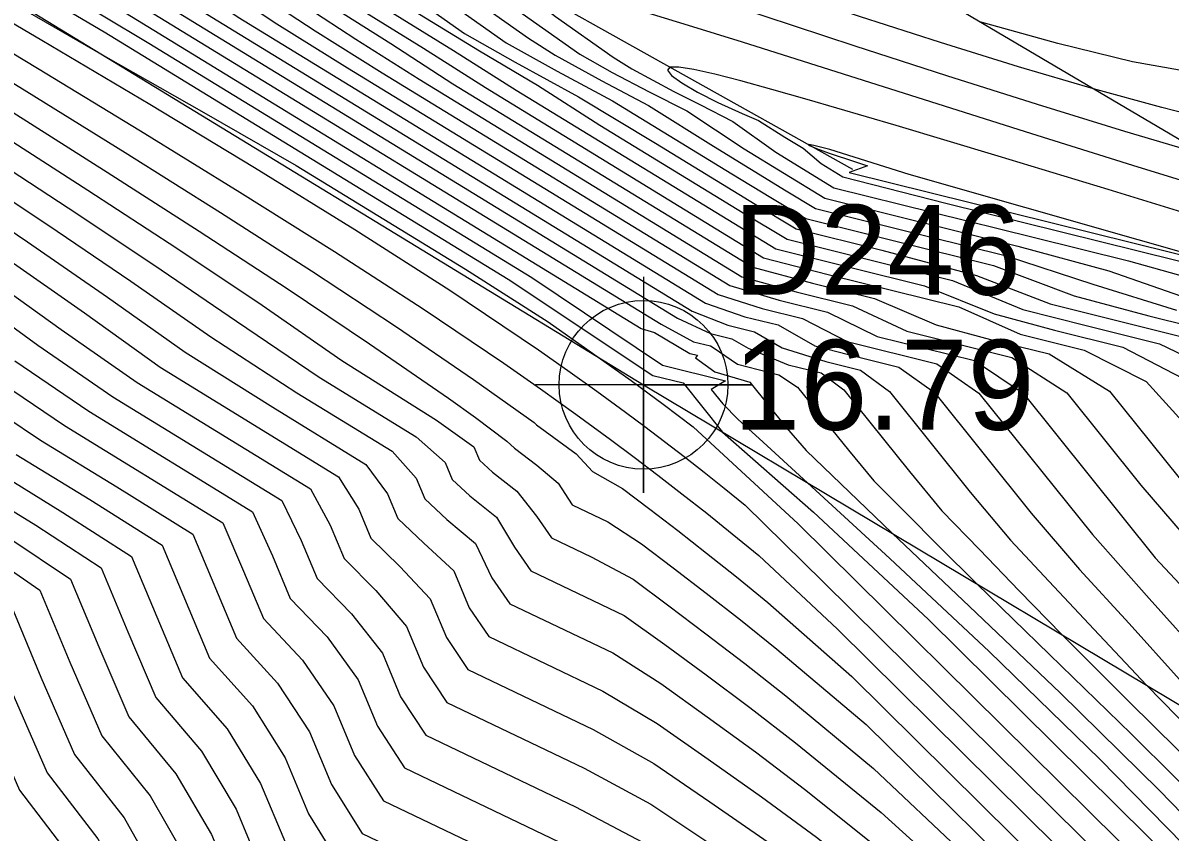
# Model space of a CAD drawing. Extents: x 2356077 to 2359823, y 225951 to 227822.
# Drawn here: x 2356785.48 to 2356817.36, y 227143.66 to 227166.13 of the extents above; entities that cross this region are included whole.
import ezdxf

# ---------------------------------------------------------------- set-up
doc = ezdxf.new("R2010")
doc.units = 0
for name, color, linetype in [('DTM Contours Major', 7, 'Continuous'), ('DTM Contours Minor', 7, 'Continuous'), ('Exist DTM Breakline', 7, 'Continuous'), ('Exist DTM Breakline Cogo Elevation', 7, 'Continuous'), ('Exist DTM Breakline Cogo Number', 7, 'Continuous'), ('Exist DTM Breakline Cogo Point CELL', 7, 'Continuous'), ('PH Exist DTM Breakline', 7, 'Continuous')]:
    doc.layers.add(name, color=color, linetype=linetype)

msp = doc.modelspace()

# ---------------------------------------------------------------- linework, layer by layer
at = {"layer": 'DTM Contours Major'}
for points in [[(2356762.219, 227179.9), (2356765.26, 227177.995), (2356768.642, 227175.932), (2356772.236, 227173.778), (2356775.914, 227171.598), (2356786.008, 227165.659), (2356789.013, 227163.876), (2356791.921, 227162.122), (2356794.706, 227160.399), (2356797.343, 227158.708), (2356799.806, 227157.053), (2356800.626, 227156.479), (2356801.429, 227155.905), (2356802.224, 227155.324), (2356802.765, 227154.92), (2356803.308, 227154.509), (2356803.856, 227154.087), (2356804.411, 227153.654), (2356804.974, 227153.206), (2356805.55, 227152.741), (2356807.71, 227150.617), (2356821.271, 227137.215)], [(2356771.984, 227179.958), (2356775.852, 227177.461), (2356779.548, 227175.08), (2356781.342, 227173.918), (2356783.11, 227172.784), (2356784.89, 227171.594), (2356788.41, 227169.279), (2356790.16, 227168.143), (2356791.913, 227167.028), (2356793.603, 227165.918), (2356795.466, 227164.749), (2356805.131, 227158.836), (2356806.495, 227158.436), (2356807.844, 227158.101), (2356809.226, 227157.423), (2356811.927, 227156.752), (2356813.277, 227155.85), (2356816.951, 227151.278), (2356818.724, 227149.377)], [(2356767.855, 227179.577), (2356770.544, 227177.875), (2356773.278, 227176.166), (2356776.01, 227174.471), (2356785.012, 227168.919), (2356787.456, 227167.428), (2356788.496, 227166.77), (2356803.217, 227157.763), (2356804.122, 227157.277), (2356804.592, 227157.161), (2356804.666, 227157.12), (2356805.342, 227156.656), (2356806.489, 227156.354), (2356807.01, 227156.02), (2356808.422, 227154.263), (2356809.132, 227153.413), (2356810.013, 227152.533), (2356810.959, 227151.581), (2356811.996, 227150.548), (2356814.009, 227148.592), (2356816.285, 227146.387), (2356818.748, 227143.942)], [(2356783.868, 227175.078), (2356790.873, 227170.131), (2356793.131, 227168.54), (2356795.667, 227166.9), (2356798.168, 227165.356), (2356799.779, 227164.404), (2356801.519, 227163.29), (2356805.494, 227160.859), (2356806.722, 227160.128), (2356811.317, 227158.983), (2356813.269, 227158.173), (2356815.035, 227157.729), (2356817.072, 227157.223), (2356819.079, 227156.258)], [(2356819.033, 227161.336), (2356816.326, 227162.173), (2356813.521, 227163.054), (2356805.476, 227165.601), (2356803.98, 227166.067), (2356802.641, 227166.471), (2356801.498, 227166.793), (2356800.586, 227167.012), (2356799.943, 227167.108), (2356799.606, 227167.062), (2356799.605, 227166.849), (2356800.282, 227166.313), (2356801.881, 227165.184), (2356802.405, 227164.857), (2356803.574, 227164.232), (2356804.317, 227163.863), (2356805.212, 227163.394), (2356806.406, 227162.545), (2356808.02, 227161.557), (2356813.554, 227160.179), (2356816.208, 227159.521), (2356818.519, 227158.881)], [(2356784.314, 227162.58), (2356786.736, 227160.999), (2356789.12, 227159.413), (2356791.416, 227157.847), (2356793.711, 227156.294), (2356796.415, 227154.635), (2356797.212, 227153.925), (2356797.409, 227153.454), (2356797.905, 227152.996), (2356798.644, 227152.402), (2356799.142, 227151.566), (2356799.597, 227150.914), (2356802.191, 227149.673), (2356803.318, 227148.87), (2356804.474, 227148.021), (2356805.684, 227147.114), (2356806.955, 227146.133), (2356809.337, 227144.195), (2356811.798, 227141.967), (2356817.043, 227136.784), (2356819.537, 227134.184)], [(2356783.887, 227158.648), (2356785.897, 227157.182), (2356787.982, 227155.747), (2356792.674, 227152.869), (2356793.218, 227151.757), (2356793.66, 227150.701), (2356794.617, 227149.721), (2356795.472, 227148.624), (2356795.978, 227147.415), (2356796.675, 227146.347), (2356800.843, 227144.354), (2356802.855, 227143.289), (2356804.699, 227142.097), (2356806.58, 227140.865), (2356808.474, 227139.568), (2356810.531, 227138.053), (2356812.554, 227136.432), (2356814.518, 227134.67), (2356816.412, 227132.798), (2356818.19, 227130.915)], [(2356784.626, 227153.744), (2356786.593, 227152.537), (2356788.502, 227151.309), (2356789.203, 227149.638), (2356789.92, 227147.94), (2356791.155, 227146.527), (2356792.086, 227145.004), (2356792.777, 227143.355), (2356793.722, 227141.795), (2356799.708, 227138.933), (2356802.548, 227137.526), (2356807.703, 227134.57), (2356810.109, 227133.112), (2356811.65, 227132.092), (2356813.083, 227131.048), (2356814.412, 227129.964), (2356815.64, 227128.825), (2356816.77, 227127.616), (2356817.805, 227126.32)], [(2356785.176, 227147.547), (2356786.156, 227145.297), (2356787.567, 227143.47), (2356788.648, 227141.507), (2356789.548, 227139.359), (2356790.681, 227137.286), (2356809.099, 227128.479), (2356811.638, 227127.056), (2356812.421, 227126.499), (2356813.148, 227125.93), (2356813.824, 227125.341)]]:
    msp.add_lwpolyline(points, dxfattribs=at)
at = {"layer": 'DTM Contours Minor'}
for points in [[(2356763.448, 227180.522), (2356766.611, 227178.547), (2356770.006, 227176.46), (2356773.528, 227174.324), (2356777.068, 227172.199), (2356781.274, 227169.698), (2356784.954, 227167.534), (2356787.74, 227165.886), (2356798.97, 227159.015), (2356802.984, 227156.343), (2356803.83, 227156.133), (2356804.927, 227154.769), (2356807.45, 227152.547), (2356810.639, 227149.566), (2356817.608, 227142.679)], [(2356764.857, 227180.262), (2356767.865, 227178.378), (2356771.032, 227176.419), (2356774.273, 227174.435), (2356777.501, 227172.474), (2356782.6, 227169.398), (2356785.484, 227167.672), (2356786.444, 227167.101), (2356788.982, 227165.574), (2356799.623, 227159.064), (2356803.257, 227156.625), (2356805.011, 227156.19), (2356804.612, 227155.954), (2356804.931, 227155.557), (2356805.361, 227155.117), (2356805.947, 227154.588), (2356807.283, 227153.362), (2356809.574, 227151.255), (2356812.334, 227148.671), (2356815.415, 227145.682), (2356818.669, 227142.358)], [(2356763.576, 227179.775), (2356768.377, 227176.748), (2356773.392, 227173.673), (2356778.427, 227170.653), (2356783.267, 227167.807), (2356787.722, 227165.233), (2356790.51, 227163.642), (2356793.078, 227162.17), (2356797.783, 227159.296), (2356800.08, 227157.835), (2356802.386, 227156.205), (2356803.271, 227155.547), (2356804.106, 227154.909), (2356807.026, 227152.215), (2356821.57, 227137.841)], [(2356766.351, 227179.927), (2356769.204, 227178.131), (2356772.152, 227176.298), (2356775.131, 227174.462), (2356778.075, 227172.658), (2356784.301, 227168.862), (2356787.587, 227166.877), (2356802.668, 227157.65), (2356803.033, 227157.53), (2356804.015, 227156.954), (2356804.226, 227156.902), (2356804.173, 227156.828), (2356804.715, 227156.445), (2356805.68, 227156.151), (2356806.699, 227154.882), (2356807.247, 227154.256), (2356807.975, 227153.559), (2356809.639, 227151.955), (2356811.79, 227149.918), (2356814.304, 227147.524), (2356817.071, 227144.812), (2356819.981, 227141.818)], [(2356775.619, 227179.873), (2356779.065, 227177.513), (2356779.966, 227176.929), (2356782.817, 227175.183), (2356783.638, 227174.674), (2356788.197, 227171.455), (2356790.455, 227169.868), (2356792.806, 227168.305), (2356795.146, 227166.792), (2356797.446, 227165.366), (2356799.194, 227164.265), (2356806.403, 227159.857), (2356810.537, 227158.831), (2356812.473, 227158.055), (2356814.153, 227157.598), (2356816.05, 227157.127), (2356817.944, 227156.145)], [(2356761.395, 227179.673), (2356764.414, 227177.783), (2356767.751, 227175.744), (2356771.274, 227173.625), (2356780.687, 227168.008), (2356782.972, 227166.636), (2356785.887, 227164.88), (2356788.747, 227163.141), (2356791.512, 227161.436), (2356794.144, 227159.781), (2356796.601, 227158.19), (2356798.845, 227156.681), (2356799.869, 227155.966), (2356800.851, 227155.263), (2356801.812, 227154.558), (2356802.467, 227154.069), (2356803.127, 227153.569), (2356803.798, 227153.051), (2356804.486, 227152.511), (2356805.194, 227151.944), (2356805.93, 227151.343), (2356808.116, 227149.293), (2356817.663, 227139.858)], [(2356769.411, 227179.181), (2356772.043, 227177.527), (2356777.119, 227174.36), (2356781.872, 227171.397), (2356785.811, 227168.932), (2356787.109, 227168.126), (2356788.412, 227167.323), (2356789.459, 227166.629), (2356803.674, 227157.932), (2356804.591, 227157.51), (2356805.188, 227157.362), (2356805.636, 227157.098), (2356806.748, 227156.64), (2356807.666, 227156.412), (2356808.299, 227155.942), (2356810.12, 227153.676), (2356811.022, 227152.584), (2356812.065, 227151.506), (2356813.166, 227150.359), (2356814.352, 227149.141), (2356816.214, 227147.286), (2356818.252, 227145.271)], [(2356773.775, 227179.147), (2356779.588, 227175.496), (2356783.202, 227173.283), (2356785.212, 227171.88), (2356789.133, 227169.309), (2356791.037, 227168.072), (2356792.916, 227166.874), (2356794.736, 227165.683), (2356796.497, 227164.568), (2356805.459, 227159.084), (2356806.971, 227158.667), (2356808.534, 227158.279), (2356810.045, 227157.569), (2356812.968, 227156.844), (2356814.493, 227155.862), (2356816.554, 227153.297), (2356818.668, 227150.83)], [(2356770.593, 227179.03), (2356773.029, 227177.493), (2356779.99, 227173.121), (2356783.62, 227170.826), (2356786.452, 227169.03), (2356787.862, 227168.143), (2356789.284, 227167.259), (2356790.445, 227166.475), (2356804.082, 227158.131), (2356805.068, 227157.742), (2356805.812, 227157.557), (2356806.579, 227157.112), (2356807.793, 227156.73), (2356808.762, 227156.489), (2356809.565, 227155.892), (2356811.811, 227153.098), (2356812.928, 227151.761), (2356814.136, 227150.476), (2356815.388, 227149.131), (2356816.708, 227147.734), (2356818.402, 227146)], [(2356771.746, 227178.895), (2356776.198, 227176.074), (2356780.444, 227173.384), (2356782.484, 227172.084), (2356787.098, 227169.121), (2356788.619, 227168.153), (2356790.152, 227167.192), (2356791.466, 227166.299), (2356804.453, 227158.353), (2356805.545, 227157.973), (2356806.467, 227157.744), (2356807.488, 227157.163), (2356808.747, 227156.842), (2356809.828, 227156.574), (2356810.814, 227155.864), (2356813.503, 227152.517), (2356814.847, 227150.947), (2356816.226, 227149.445), (2356817.625, 227147.897)], [(2356772.866, 227178.78), (2356778.958, 227174.891), (2356780.899, 227173.647), (2356782.8, 227172.422), (2356787.751, 227169.203), (2356789.385, 227168.154), (2356791.028, 227167.116), (2356792.535, 227166.107), (2356794.505, 227164.889), (2356804.8, 227158.59), (2356806.022, 227158.204), (2356807.15, 227157.924), (2356808.393, 227157.28), (2356810.881, 227156.662), (2356812.05, 227155.851), (2356815.211, 227151.918), (2356816.781, 227150.147), (2356818.333, 227148.418)], [(2356775.337, 227178.722), (2356778.591, 227176.664), (2356783.352, 227173.745), (2356785.471, 227172.249), (2356787.578, 227170.827), (2356789.651, 227169.455), (2356791.693, 227168.119), (2356793.708, 227166.829), (2356795.706, 227165.564), (2356797.429, 227164.446), (2356805.767, 227159.345), (2356807.428, 227158.904), (2356809.145, 227158.478), (2356810.86, 227157.75), (2356812.373, 227157.341), (2356814.002, 227156.937), (2356815.684, 227155.906), (2356817.996, 227153.028)], [(2356776.165, 227178.813), (2356777.1, 227178.182), (2356778.353, 227177.376), (2356779.746, 227176.509), (2356783.501, 227174.206), (2356787.919, 227171.085), (2356790.124, 227169.597), (2356792.316, 227168.148), (2356794.481, 227166.752), (2356796.61, 227165.435), (2356798.337, 227164.339), (2356806.065, 227159.612), (2356807.861, 227159.146), (2356811.493, 227158.244), (2356813.194, 227157.487), (2356814.979, 227157.044), (2356816.694, 227156.175), (2356818.889, 227153.762)], [(2356784.197, 227175.682), (2356785.675, 227174.367), (2356797.754, 227165.837), (2356799.163, 227165.047), (2356800.922, 227164.083), (2356803.064, 227162.794), (2356805.836, 227161.098), (2356806.968, 227160.416), (2356809.351, 227159.824), (2356811.979, 227159.118), (2356814.03, 227158.328), (2356818.108, 227157.316)], [(2356789.115, 227172.503), (2356798.916, 227165.582), (2356800.332, 227164.792), (2356801.866, 227163.969), (2356805.182, 227161.947), (2356806.265, 227161.284), (2356807.244, 227160.697), (2356809.744, 227160.076), (2356812.453, 227159.393), (2356814.693, 227158.557), (2356816.772, 227157.997), (2356819.089, 227157.422)], [(2356818.938, 227163.323), (2356817.135, 227163.781), (2356815.235, 227164.302), (2356813.153, 227164.914), (2356810.979, 227165.587), (2356808.735, 227166.31), (2356806.443, 227167.069), (2356804.126, 227167.852), (2356801.805, 227168.646), (2356799.677, 227169.334), (2356793.597, 227171.275), (2356792.422, 227171.491), (2356791.901, 227171.372), (2356792.524, 227170.661), (2356799.529, 227165.714), (2356800.272, 227165.235), (2356801.568, 227164.522), (2356802.865, 227163.844), (2356804.673, 227162.708), (2356806.693, 227161.472), (2356807.51, 227160.98), (2356812.776, 227159.673), (2356815.217, 227158.875), (2356817.538, 227158.156)], [(2356818.391, 227162.44), (2356816.103, 227163.116), (2356813.674, 227163.865), (2356811.158, 227164.666), (2356808.609, 227165.493), (2356806.08, 227166.326), (2356803.625, 227167.14), (2356801.721, 227167.756), (2356799.957, 227168.319), (2356798.309, 227168.838), (2356797.054, 227169.163), (2356796.178, 227169.302), (2356795.754, 227169.217), (2356795.932, 227168.82), (2356800.959, 227165.27), (2356801.861, 227164.76), (2356802.886, 227164.217), (2356803.932, 227163.692), (2356805.528, 227162.633), (2356807.768, 227161.266), (2356813.136, 227159.934), (2356815.661, 227159.248), (2356818.051, 227158.416)], [(2356756.185, 227168.705), (2356757.309, 227168.129), (2356758.424, 227167.522), (2356759.539, 227166.88), (2356760.663, 227166.2), (2356761.807, 227165.477), (2356762.98, 227164.709), (2356764.896, 227163.405), (2356766.782, 227161.973), (2356774.949, 227155.672), (2356776.253, 227154.7), (2356778.997, 227152.323), (2356782.076, 227150.434), (2356783.404, 227149.434), (2356784.365, 227147.141), (2356785.383, 227144.822), (2356786.82, 227142.938), (2356787.939, 227140.859), (2356788.888, 227138.594), (2356790.023, 227136.408), (2356809.655, 227127.02), (2356812.033, 227125.745)], [(2356818.359, 227164.697), (2356816.316, 227165.054), (2356814.24, 227165.568), (2356812.078, 227166.164)], [(2356782.826, 227165.928), (2356785.591, 227164.23), (2356788.323, 227162.535), (2356790.977, 227160.866), (2356793.506, 227159.243), (2356795.863, 227157.69), (2356798, 227156.228), (2356799.689, 227155.036), (2356799.753, 227154.973), (2356800.856, 227154.161), (2356801.308, 227153.674), (2356802.148, 227153.197), (2356802.905, 227152.625), (2356803.68, 227152.032), (2356804.48, 227151.408), (2356805.314, 227150.745), (2356806.188, 227150.034), (2356808.518, 227147.974), (2356817.481, 227139.116)], [(2356818.776, 227160.546), (2356815.642, 227161.506), (2356812.586, 227162.435), (2356809.749, 227163.285), (2356807.274, 227164.01), (2356806.294, 227164.289), (2356805.434, 227164.525), (2356804.707, 227164.712), (2356804.127, 227164.842), (2356803.706, 227164.909), (2356803.459, 227164.907), (2356803.393, 227164.827), (2356803.511, 227164.677), (2356803.796, 227164.468), (2356804.23, 227164.214), (2356804.795, 227163.926), (2356805.473, 227163.617), (2356805.922, 227163.428), (2356806.655, 227162.959), (2356807.166, 227162.66), (2356807.663, 227162.225), (2356808.268, 227161.855), (2356811.132, 227161.13), (2356819.691, 227159.006)], [(2356785.206, 227163.647), (2356787.825, 227161.993), (2356790.382, 227160.354), (2356792.827, 227158.753), (2356795.109, 227157.215), (2356797.311, 227155.711), (2356798.06, 227155.171), (2356798.926, 227154.516), (2356799.146, 227154.317), (2356799.765, 227153.851), (2356800.356, 227153.35), (2356800.745, 227152.75), (2356801.74, 227152.275), (2356802.674, 227151.662), (2356803.554, 227150.997), (2356804.468, 227150.296), (2356805.424, 227149.547), (2356806.432, 227148.737), (2356808.921, 227146.648), (2356814.351, 227141.288), (2356817.321, 227138.353), (2356820.115, 227135.477)], [(2356784.774, 227163.103), (2356787.29, 227161.486), (2356789.758, 227159.874), (2356792.126, 227158.291), (2356794.345, 227156.76), (2356796.979, 227155.102), (2356798.01, 227154.362), (2356798.166, 227153.988), (2356798.531, 227153.656), (2356799.21, 227153.129), (2356799.759, 227152.435), (2356800.174, 227151.831), (2356801.277, 227151.303), (2356802.442, 227150.679), (2356803.433, 227149.943), (2356804.464, 227149.167), (2356805.546, 227148.337), (2356806.686, 227147.438), (2356809.12, 227145.425), (2356811.617, 227143.068), (2356817.176, 227137.573), (2356819.819, 227134.834)], [(2356819.687, 227159.189), (2356810.116, 227161.921), (2356807.91, 227162.619), (2356807.462, 227162.734), (2356807.374, 227162.752), (2356807.323, 227162.758), (2356807.311, 227162.752), (2356807.343, 227162.731), (2356807.538, 227162.648), (2356807.886, 227162.52), (2356808.588, 227162.283), (2356808.952, 227162.167), (2356808.447, 227161.978), (2356819.687, 227159.189)], [(2356783.839, 227162.072), (2356786.173, 227160.523), (2356788.477, 227158.963), (2356790.703, 227157.413), (2356793.097, 227155.859), (2356795.744, 227154.234), (2356796.414, 227153.489), (2356796.655, 227152.914), (2356797.267, 227152.338), (2356798.064, 227151.674), (2356798.517, 227150.719), (2356799.016, 227149.999), (2356801.879, 227148.63), (2356803.212, 227147.78), (2356804.496, 227146.859), (2356805.837, 227145.88), (2356807.238, 227144.822), (2356809.566, 227142.962), (2356811.977, 227140.869), (2356816.915, 227135.988), (2356819.263, 227133.532)], [(2356783.354, 227161.571), (2356785.606, 227160.054), (2356787.832, 227158.52), (2356789.989, 227156.986), (2356792.429, 227155.456), (2356795.016, 227153.869), (2356795.616, 227153.055), (2356795.903, 227152.37), (2356796.619, 227151.683), (2356797.454, 227150.913), (2356797.886, 227149.884), (2356798.433, 227149.085), (2356801.597, 227147.572), (2356803.112, 227146.675), (2356804.53, 227145.684), (2356806.004, 227144.636), (2356807.533, 227143.509), (2356809.804, 227141.73), (2356812.135, 227139.761), (2356814.453, 227137.5), (2356816.791, 227135.189), (2356818.994, 227132.878)], [(2356785.038, 227159.589), (2356787.19, 227158.08), (2356789.293, 227156.567), (2356794.252, 227153.525), (2356794.816, 227152.623), (2356795.152, 227151.821), (2356795.961, 227151.03), (2356796.802, 227150.131), (2356797.251, 227149.058), (2356797.847, 227148.172), (2356801.334, 227146.505), (2356803.019, 227145.557), (2356804.576, 227144.498), (2356807.817, 227142.251), (2356810.046, 227140.499), (2356812.278, 227138.645), (2356814.48, 227136.551), (2356816.667, 227134.389), (2356818.727, 227132.224)], [(2356784.464, 227159.106), (2356786.541, 227157.616), (2356788.653, 227156.148), (2356793.476, 227153.189), (2356794.019, 227152.185), (2356794.409, 227151.254), (2356795.29, 227150.368), (2356796.14, 227149.369), (2356796.616, 227148.234), (2356797.263, 227147.259), (2356801.084, 227145.432), (2356802.933, 227144.428), (2356804.632, 227143.302), (2356806.377, 227142.127), (2356808.15, 227140.908), (2356810.289, 227139.274), (2356812.418, 227137.536), (2356814.503, 227135.606), (2356816.542, 227133.591), (2356818.459, 227131.57)], [(2356785.255, 227156.747), (2356787.311, 227155.346), (2356791.861, 227152.555), (2356792.416, 227151.33), (2356792.912, 227150.147), (2356793.937, 227149.076), (2356794.8, 227147.889), (2356795.34, 227146.6), (2356796.087, 227145.436), (2356800.609, 227143.273), (2356802.782, 227142.143), (2356804.775, 227140.886), (2356806.792, 227139.6), (2356808.8, 227138.259), (2356810.77, 227136.84), (2356812.682, 227135.335), (2356814.521, 227133.74), (2356816.276, 227132.01), (2356817.917, 227130.26)], [(2356784.617, 227156.312), (2356786.64, 227154.946), (2356791.041, 227152.246), (2356791.613, 227150.905), (2356792.164, 227149.592), (2356793.25, 227148.434), (2356794.124, 227147.161), (2356794.7, 227145.786), (2356795.498, 227144.525), (2356800.381, 227142.19), (2356802.716, 227140.99), (2356804.859, 227139.672), (2356807.012, 227138.336), (2356809.128, 227136.957), (2356811.003, 227135.635), (2356812.801, 227134.247), (2356814.513, 227132.786), (2356816.13, 227131.232), (2356817.64, 227129.603)], [(2356783.98, 227155.876), (2356785.969, 227154.545), (2356788.088, 227153.245), (2356790.201, 227151.935), (2356791.415, 227149.039), (2356792.557, 227147.795), (2356793.446, 227146.438), (2356794.06, 227144.974), (2356794.907, 227143.614), (2356800.155, 227141.105), (2356802.655, 227139.835), (2356804.951, 227138.456), (2356807.237, 227137.074), (2356809.457, 227135.663), (2356811.229, 227134.441), (2356812.909, 227133.17), (2356814.494, 227131.838), (2356815.978, 227130.433), (2356817.358, 227128.944), (2356818.63, 227127.359)], [(2356785.297, 227154.145), (2356787.342, 227152.89), (2356789.352, 227151.622), (2356790.666, 227148.487), (2356791.859, 227147.16), (2356792.767, 227145.719), (2356793.419, 227144.164), (2356794.316, 227142.704), (2356799.932, 227140.019), (2356802.599, 227138.679), (2356805.049, 227137.242), (2356807.468, 227135.817), (2356809.785, 227134.38), (2356811.445, 227133.259), (2356813.004, 227132.103), (2356814.461, 227130.897), (2356815.816, 227129.629), (2356817.068, 227128.282), (2356818.219, 227126.845)], [(2356783.955, 227153.343), (2356785.843, 227152.185), (2356787.653, 227150.996), (2356788.398, 227149.217), (2356789.174, 227147.398), (2356790.447, 227145.899), (2356791.404, 227144.292), (2356792.135, 227142.548), (2356793.127, 227140.887), (2356799.48, 227137.849), (2356802.501, 227136.383), (2356807.939, 227133.338), (2356810.428, 227131.861), (2356811.84, 227130.942), (2356813.143, 227130.006), (2356814.345, 227129.038), (2356815.449, 227128.022), (2356816.46, 227126.942), (2356817.384, 227125.781)], [(2356785.092, 227151.833), (2356786.803, 227150.684), (2356787.594, 227148.798), (2356788.424, 227146.861), (2356789.735, 227145.275), (2356790.72, 227143.584), (2356791.491, 227141.743), (2356792.528, 227139.981), (2356802.441, 227135.241), (2356805.372, 227133.663), (2356808.174, 227132.128), (2356810.74, 227130.631), (2356812.012, 227129.81), (2356813.182, 227128.978), (2356814.256, 227128.119), (2356815.238, 227127.217), (2356816.136, 227126.258), (2356816.956, 227125.224)], [(2356784.339, 227151.483), (2356785.954, 227150.371), (2356786.788, 227148.379), (2356787.672, 227146.33), (2356789.018, 227144.659), (2356790.034, 227142.882), (2356790.846, 227140.941), (2356791.923, 227139.077), (2356802.357, 227134.088), (2356805.483, 227132.523), (2356808.407, 227130.951), (2356811.042, 227129.424), (2356812.166, 227128.698), (2356813.197, 227127.962), (2356814.141, 227127.203), (2356815.005, 227126.406), (2356815.794, 227125.558)], [(2356785.104, 227150.058), (2356785.983, 227147.962), (2356786.917, 227145.807), (2356788.297, 227144.053), (2356789.344, 227142.187), (2356790.2, 227140.145), (2356791.31, 227138.178), (2356805.618, 227131.336), (2356808.634, 227129.821), (2356811.336, 227128.239), (2356812.299, 227127.602), (2356813.184, 227126.954), (2356813.997, 227126.284), (2356814.743, 227125.582)]]:
    msp.add_lwpolyline(points, dxfattribs=at)
at = {"layer": 'Exist DTM Breakline'}
msp.add_lwpolyline([(2356613.053, 227270.361), (2356650.333, 227243.926), (2356697.977, 227215.131), (2356733.42, 227198.56), (2356756.55, 227184.242), (2356802.729, 227156.081), (2356830.777, 227139.335)], dxfattribs=at)
at = {"layer": 'Exist DTM Breakline Cogo Point CELL'}
msp.add_lwpolyline([(2356802.729, 227159.081), (2356802.729, 227153.081), (2356802.729, 227156.081), (2356805.729, 227156.081), (2356799.729, 227156.081)], dxfattribs=at)
msp.add_circle((2356802.729, 227156.081), 2.344, dxfattribs=at)
at = {"layer": 'PH Exist DTM Breakline'}
for points in [[(2356874.006, 227127.776), (2356827.187, 227157.253), (2356798.45, 227174.201), (2356773.903, 227189.099), (2356754.358, 227199.973), (2356736.653, 227209.957), (2356718.488, 227220.641), (2356700.429, 227231.907), (2356681.257, 227242.915), (2356663.176, 227254.535), (2356644.166, 227266.793), (2356622.923, 227279.772), (2356610.333, 227287.071), (2356602.922, 227291.069), (2356601.494, 227294.51)], [(2356595.251, 227285.48), (2356610.292, 227279.585), (2356630.224, 227267.853), (2356651.648, 227254.925), (2356672.172, 227242.038), (2356694.087, 227228.261), (2356715.804, 227214.703), (2356738.018, 227201.132), (2356760.194, 227188.688), (2356783.837, 227175.884), (2356808.534, 227162.068)]]:
    msp.add_lwpolyline(points, dxfattribs=at)

# ---------------------------------------------------------------- texts
at = {"layer": 'Exist DTM Breakline Cogo Elevation'}
msp.add_text('16.79', height=2.5, dxfattribs=at).set_placement((2356805.229, 227154.831))
at = {"layer": 'Exist DTM Breakline Cogo Number'}
msp.add_text('D246', height=2.5, dxfattribs=at).set_placement((2356805.229, 227158.581))

doc.saveas('drawing.dxf')
